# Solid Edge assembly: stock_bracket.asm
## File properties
Author: Deepak Maini
Template: Normal.asm
Last saved by: MYPC
Revision: 27
Application: Solid Edge
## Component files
adjusting_screw_guide.par
adjusting_nut_handle.par
stock_support_roller.par
Stock_support_base.par
thrust_bearing.par
adjusting_screw_nut.par
support_adjusting_screw.par
support_roller_bracket.par
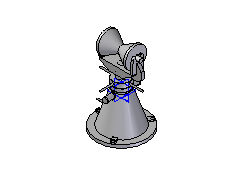
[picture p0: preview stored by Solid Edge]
